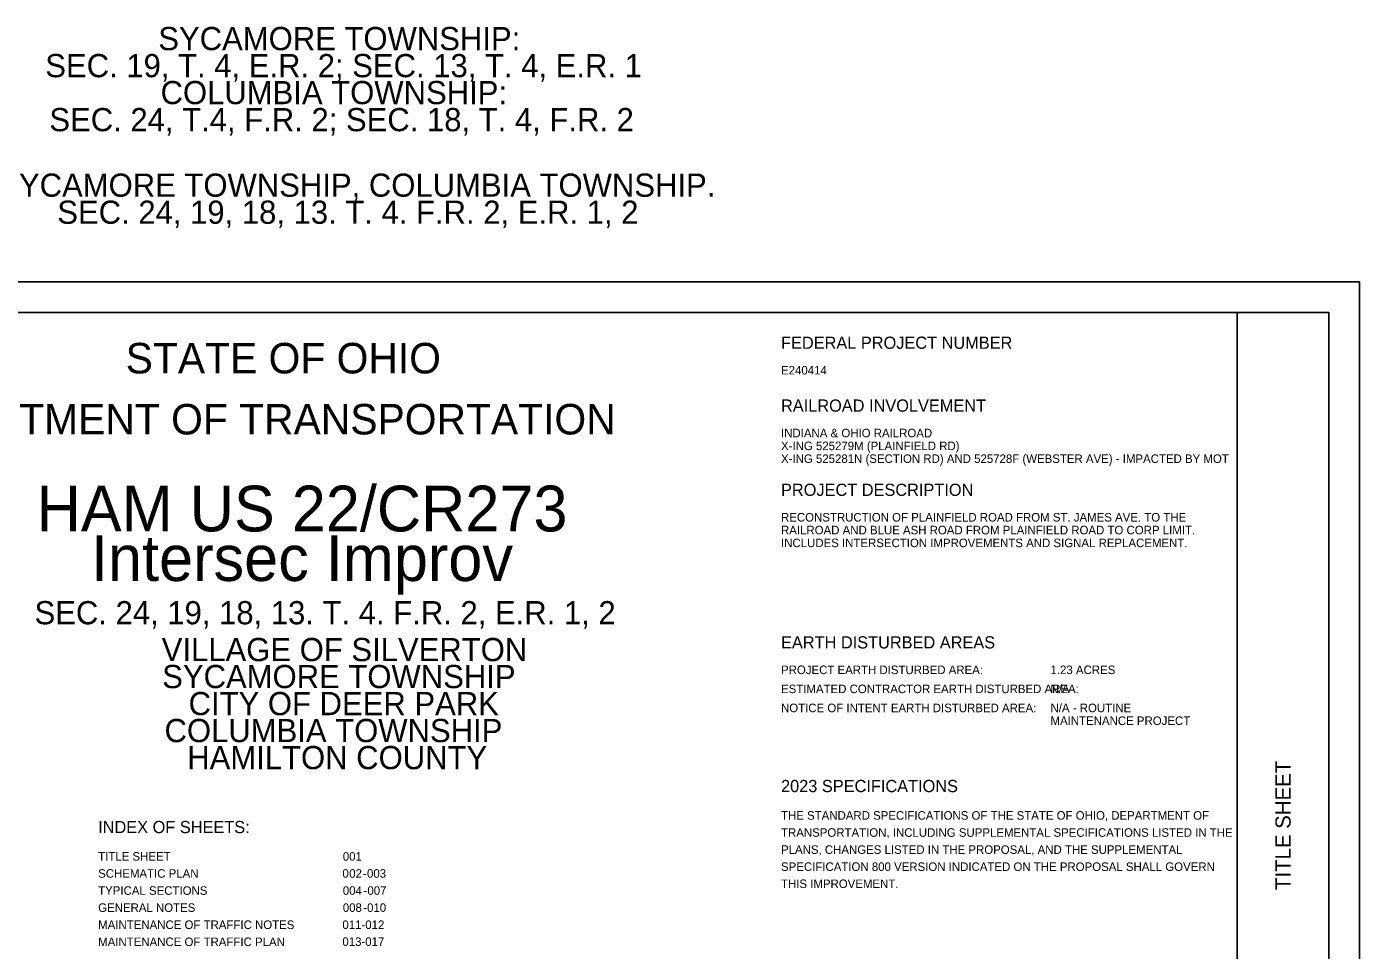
# Model space of a CAD drawing. Extents: x 0 to 34, y -3.9 to 26.2.
# Drawn here: x 12.17 to 34, y 11.05 to 26.18 of the extents above; entities that cross this region are included whole.
import ezdxf

# ---------------------------------------------------------------- set-up
doc = ezdxf.new("R2010")
doc.units = 0
for name, color, linetype in [('SH_Border', 7, 'Continuous'), ('SH_Cut_Line', 7, 'Continuous'), ('SH_Data', 7, 'Continuous'), ('SH_Text', 7, 'Continuous')]:
    doc.layers.add(name, color=color, linetype=linetype)

msp = doc.modelspace()

# ---------------------------------------------------------------- linework, layer by layer
at = {"layer": 'SH_Border'}
msp.add_line((32, 0.5), (32, 21.5), dxfattribs=at)
msp.add_lwpolyline([(1.5, 21.5), (33.5, 21.5), (33.5, 0.5), (1.5, 0.5)], close=True, dxfattribs=at)
at = {"layer": 'SH_Cut_Line'}
msp.add_lwpolyline([(0, 0), (34, 0), (34, 22), (0, 22)], close=True, dxfattribs=at)

# ---------------------------------------------------------------- texts
at = {"layer": 'SH_Data'}
msp.add_text('TITLE SHEET', height=0.25, rotation=90, dxfattribs=at).set_placement((32.875, 12.035))
at = {"layer": 'SH_Text'}
for s, height, p in [('SYCAMORE TOWNSHIP:', 0.38, (14.329, 25.797)), ('SEC. 19, T. 4, E.R. 2; SEC. 13, T. 4, E.R. 1', 0.38, (12.478, 25.354)), ('COLUMBIA TOWNSHIP:', 0.38, (14.366, 24.912)), ('SEC. 24, T.4, F.R. 2; SEC. 18, T. 4, F.R. 2', 0.38, (12.545, 24.469)), ('SYCAMORE TOWNSHIP, COLUMBIA TOWNSHIP. ', 0.38, (11.708, 23.395)), ('SEC. 24, 19, 18, 13. T. 4. F.R. 2, E.R. 1, 2 ', 0.38, (12.675, 22.952)), ('STATE OF OHIO', 0.5, (13.795, 20.5)), ('FEDERAL PROJECT NUMBER', 0.2, (24.528, 20.903)), ('E240414', 0.14, (24.528, 20.483)), ('DEPARTMENT OF TRANSPORTATION', 0.5, (9.747, 19.5)), ('RAILROAD INVOLVEMENT', 0.2, (24.528, 19.873)), ('INDIANA & OHIO RAILROAD', 0.14, (24.528, 19.453)), ('X-ING 525279M (PLAINFIELD RD) ', 0.14, (24.528, 19.243)), ('X-ING 525281N (SECTION RD) AND 525728F (WEBSTER AVE) - IMPACTED BY MOT', 0.14, (24.528, 19.033)), ('HAM US 22/CR273', 0.75, (12.336, 17.911)), ('PROJECT DESCRIPTION', 0.2, (24.528, 18.493)), ('RECONSTRUCTION OF PLAINFIELD ROAD FROM ST. JAMES AVE. TO THE ', 0.14, (24.528, 18.073)), ('RAILROAD AND BLUE ASH ROAD FROM PLAINFIELD ROAD TO CORP LIMIT. ', 0.14, (24.528, 17.863)), (' Intersec Improv', 0.75, (12.948, 17.099)), ('INCLUDES INTERSECTION IMPROVEMENTS AND SIGNAL REPLACEMENT. ', 0.14, (24.528, 17.653)), ('SEC. 24, 19, 18, 13. T. 4. F.R. 2, E.R. 1, 2 ', 0.38, (12.302, 16.389)), ('VILLAGE OF SILVERTON', 0.38, (14.385, 15.785)), ('EARTH DISTURBED AREAS', 0.2, (24.528, 15.993)), ('SYCAMORE TOWNSHIP', 0.38, (14.393, 15.343)), ('PROJECT EARTH DISTURBED AREA:', 0.14, (24.528, 15.573)), ('1.23 ACRES', 0.14, (28.942, 15.573)), ('CITY OF DEER PARK', 0.38, (14.825, 14.9)), ('ESTIMATED CONTRACTOR EARTH DISTURBED AREA:', 0.14, (24.528, 15.261)), ('N/A', 0.14, (28.942, 15.261)), ('NOTICE OF INTENT EARTH DISTURBED AREA:', 0.14, (24.528, 14.949)), ('N/A - ROUTINE ', 0.14, (28.942, 14.949)), ('COLUMBIA TOWNSHIP', 0.38, (14.431, 14.458)), ('MAINTENANCE PROJECT', 0.14, (28.942, 14.739)), (' HAMILTON COUNTY', 0.38, (14.662, 14.015)), ('2023 SPECIFICATIONS', 0.2, (24.528, 13.639)), ('THE STANDARD SPECIFICATIONS OF THE STATE OF OHIO, DEPARTMENT OF ', 0.14, (24.528, 13.187)), ('INDEX OF SHEETS:', 0.2, (13.344, 12.967)), ('TRANSPORTATION, INCLUDING SUPPLEMENTAL SPECIFICATIONS LISTED IN THE ', 0.14, (24.528, 12.907)), ('PLANS, CHANGES LISTED IN THE PROPOSAL, AND THE SUPPLEMENTAL ', 0.14, (24.528, 12.627)), ('TITLE SHEET', 0.14, (13.344, 12.516)), ('001', 0.14, (17.351, 12.516)), ('SPECIFICATION 800 VERSION INDICATED ON THE PROPOSAL SHALL GOVERN ', 0.14, (24.528, 12.347)), ('SCHEMATIC PLAN', 0.14, (13.344, 12.236)), ('0', 0.14, (17.344, 12.236)), ('02', 0.14, (17.456, 12.236)), ('-', 0.14, (17.679, 12.236)), ('003', 0.14, (17.747, 12.236)), ('TYPICAL SECTIONS', 0.14, (13.344, 11.956)), ('004', 0.14, (17.351, 11.956)), ('-', 0.14, (17.686, 11.956)), ('007', 0.14, (17.754, 11.956)), ('THIS IMPROVEMENT.', 0.14, (24.528, 12.067)), ('GENERAL NOTES', 0.14, (13.344, 11.676)), ('008', 0.14, (17.351, 11.676)), ('-010', 0.14, (17.686, 11.676)), ('MAINTENANCE OF TRAFFIC NOTES', 0.14, (13.344, 11.396)), ('011-012', 0.14, (17.344, 11.396)), ('MAINTENANCE OF TRAFFIC PLAN', 0.14, (13.344, 11.116)), ('013-017', 0.14, (17.344, 11.119))]:
    msp.add_text(s, height=height, dxfattribs=at).set_placement(p)

doc.saveas('drawing.dxf')
